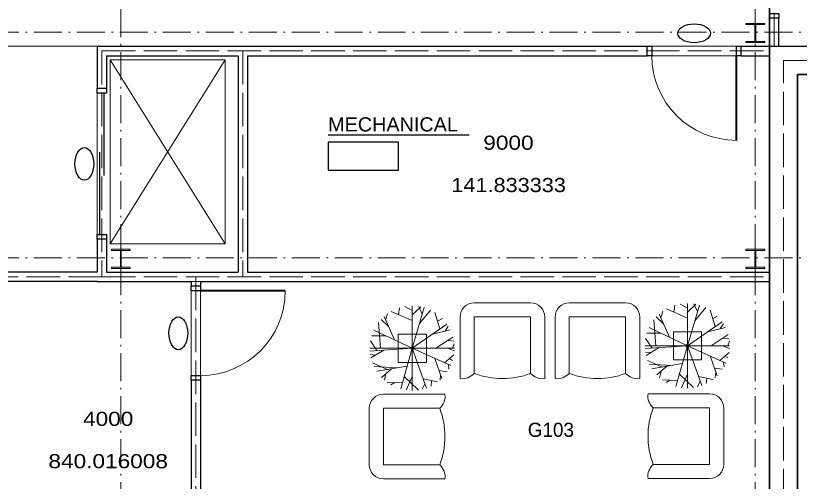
# Model space of a CAD drawing. Extents: x -118748 to -117136, y -118748 to -117596.
# Drawn here: x -117726.1 to -117459.3, y -118491.2 to -118332.8 of the extents above; entities that cross this region are included whole.
import ezdxf
from ezdxf.enums import TextEntityAlignment as Align

# ---------------------------------------------------------------- set-up
doc = ezdxf.new("R2010")
doc.units = 0
doc.header["$LTSCALE"] = 1.9
doc.header["$PDMODE"] = 32
doc.header["$PDSIZE"] = 0.95
doc.linetypes.add('DOT_DASHED', pattern=[7.7, 5, -1.2, 0.3, -1.2])
doc.linetypes.add('LONG_DASHED', pattern=[7.5, 6, -1.5])
for name, color, linetype, lineweight in [('10', 7, 'DOT_DASHED', 13), ('12', 7, 'Continuous', 13), ('15', 7, 'Continuous', 13), ('17', 7, 'Continuous', 25), ('18', 7, 'Continuous', 13), ('23', 7, 'Continuous', 25), ('25', 7, 'Continuous', 13), ('26', 7, 'Continuous', 25), ('3', 7, 'Continuous', 35), ('30', 7, 'Continuous', 13), ('4', 7, 'Continuous', 35), ('42', 7, 'Continuous', 25), ('45', 7, 'Continuous', 25), ('5', 7, 'Continuous', 13), ('6', 7, 'Continuous', 13), ('60', 7, 'LONG_DASHED', 13), ('9', 7, 'Continuous', 35)]:
    doc.layers.add(name, color=color, linetype=linetype, lineweight=lineweight)

msp = doc.modelspace()

# ---------------------------------------------------------------- linework, layer by layer
at = {"layer": '10'}
for p, q in [((-117690.321, -117628.339), (-117690.321, -118698.41)), ((-117474.321, -117628.339), (-117474.321, -118698.41)), ((-118641.571, -118338.41), (-117285.521, -118338.41)), ((-118641.571, -118415.21), (-117285.521, -118415.21))]:
    msp.add_line(p, q, dxfattribs=at)
at = {"layer": '12'}
for points in [[(-117477.504, -118341.962), (-117471.088, -118341.962), (-117471.088, -118341.566), (-117474.172, -118341.566), (-117474.172, -118335.862), (-117471.088, -118335.862), (-117471.088, -118335.466), (-117477.504, -118335.466), (-117477.504, -118335.862), (-117474.42, -118335.862), (-117474.42, -118341.566), (-117477.504, -118341.566)], [(-117693.504, -118418.762), (-117687.088, -118418.762), (-117687.088, -118418.366), (-117690.172, -118418.366), (-117690.172, -118412.662), (-117687.088, -118412.662), (-117687.088, -118412.266), (-117693.504, -118412.266), (-117693.504, -118412.662), (-117690.42, -118412.662), (-117690.42, -118418.366), (-117693.504, -118418.366)], [(-117477.504, -118418.762), (-117471.088, -118418.762), (-117471.088, -118418.366), (-117474.172, -118418.366), (-117474.172, -118412.662), (-117471.088, -118412.662), (-117471.088, -118412.266), (-117477.504, -118412.266), (-117477.504, -118412.662), (-117474.42, -118412.662), (-117474.42, -118418.366), (-117477.504, -118418.366)]]:
    msp.add_lwpolyline(points, close=True, dxfattribs=at)
at = {"layer": '15', "lineweight": 25}
for p, q in [((-117469.521, -118343.21), (-117379.921, -118343.21)), ((-117469.521, -118492.01), (-117469.521, -118343.21)), ((-117459.921, -118352.81), (-117370.321, -118352.81)), ((-117459.921, -118492.01), (-117459.921, -118352.81))]:
    msp.add_line(p, q, dxfattribs=at)
at = {"layer": '15'}
for p, q in [((-117550.78, -118430.474), (-117569.98, -118430.474)), ((-117518.446, -118430.474), (-117537.646, -118430.474)), ((-117574.78, -118435.274), (-117574.78, -118456.259)), ((-117545.98, -118456.259), (-117545.98, -118435.274)), ((-117542.446, -118435.274), (-117542.446, -118456.259)), ((-117513.646, -118456.259), (-117513.646, -118435.274)), ((-117579.946, -118461.557), (-117600.932, -118461.557)), ((-117489.85, -118461.426), (-117510.836, -118461.426)), ((-117605.732, -118466.357), (-117605.732, -118485.557)), ((-117485.05, -118485.426), (-117485.05, -118466.226)), ((-117600.932, -118490.357), (-117579.946, -118490.357)), ((-117510.836, -118490.226), (-117489.85, -118490.226))]:
    msp.add_line(p, q, dxfattribs=at)
for points in [[(-117550.78, -118454.474), (-117550.78, -118435.274), (-117569.98, -118435.274), (-117569.98, -118454.474)], [(-117518.446, -118454.474), (-117518.446, -118435.274), (-117537.646, -118435.274), (-117537.646, -118454.474)], [(-117581.732, -118466.357), (-117600.932, -118466.357), (-117600.932, -118485.557), (-117581.732, -118485.557)], [(-117509.05, -118485.426), (-117489.85, -118485.426), (-117489.85, -118466.226), (-117509.05, -118466.226)]]:
    msp.add_lwpolyline(points, dxfattribs=at)
for centre, radius, start, end in [((-117569.98, -118435.274), 4.8, 90, 180), ((-117550.78, -118435.274), 4.8, 360, 90), ((-117537.646, -118435.274), 4.8, 90, 180), ((-117518.446, -118435.274), 4.8, 360, 90), ((-117574.085, -118450.782), 5.521, 262.77334, 318.03706), ((-117560.38, -118429.56), 26.699, 248.92678, 291.07322), ((-117546.674, -118450.782), 5.521, 221.96294, 277.22666), ((-117541.752, -118450.782), 5.521, 262.77334, 318.03706), ((-117528.046, -118429.56), 26.699, 248.92678, 291.07322), ((-117514.341, -118450.782), 5.521, 221.96294, 277.22666), ((-117600.932, -118466.357), 4.8, 90, 180), ((-117585.423, -118462.252), 5.521, 311.96294, 7.22666), ((-117505.358, -118462.12), 5.521, 172.77334, 228.03706), ((-117489.85, -118466.226), 4.8, 360, 90), ((-117606.645, -118475.957), 26.699, 338.92678, 21.07322), ((-117484.136, -118475.826), 26.699, 158.92678, 201.07321), ((-117600.932, -118485.557), 4.8, 180, 270), ((-117585.423, -118489.663), 5.521, 352.77334, 48.03706), ((-117505.358, -118489.531), 5.521, 131.96294, 187.22666), ((-117489.85, -118485.426), 4.8, 270, 0)]:
    msp.add_arc(centre, radius, start, end, dxfattribs=at)
at = {"layer": '17'}
msp.add_line((-117619.741, -118373.375), (-117571.741, -118373.375), dxfattribs=at)
at = {"layer": '18'}
for p, q in [((-117693.869, -118347.778), (-117654.831, -118410.353)), ((-117693.869, -118410.353), (-117654.831, -118347.778))]:
    msp.add_line(p, q, dxfattribs=at)
msp.add_lwpolyline([(-117693.869, -118347.778), (-117693.869, -118410.353), (-117654.831, -118410.353), (-117654.831, -118347.778)], close=True, dxfattribs=at)
at = {"layer": '23'}
for p, q in [((-117466.321, -118333.61), (-117469.521, -118333.61)), ((-117469.521, -118343.21), (-117469.521, -118333.61)), ((-117466.321, -118343.21), (-117466.321, -118333.61)), ((-117698.321, -118343.21), (-117698.321, -118357.61)), ((-117698.321, -118343.21), (-117511.121, -118343.21)), ((-117511.121, -118346.41), (-117511.121, -118343.21)), ((-117479.121, -118346.41), (-117479.121, -118343.21)), ((-117479.121, -118343.21), (-117469.521, -118343.21)), ((-117469.521, -118343.21), (-117466.321, -118343.21)), ((-117695.121, -118346.41), (-117650.321, -118346.41)), ((-117695.121, -118346.41), (-117695.121, -118357.61)), ((-117650.321, -118346.41), (-117650.321, -118420.01)), ((-117647.121, -118346.41), (-117647.121, -118420.01)), ((-117647.121, -118346.41), (-117511.121, -118346.41)), ((-117479.121, -118346.41), (-117469.521, -118346.41)), ((-117695.121, -118357.61), (-117698.321, -118357.61)), ((-117695.121, -118408.81), (-117698.321, -118408.81)), ((-117698.321, -118408.81), (-117698.321, -118420.01)), ((-117695.121, -118408.81), (-117695.121, -118420.01)), ((-117698.321, -118420.01), (-117843.25, -118420.01)), ((-117695.121, -118420.01), (-117650.321, -118420.01)), ((-117647.121, -118420.01), (-117469.521, -118420.01)), ((-117469.521, -118420.01), (-117469.521, -118423.21)), ((-117698.321, -118423.21), (-117840.35, -118423.21)), ((-117698.321, -118423.21), (-117666.321, -118423.21)), ((-117666.321, -118423.21), (-117666.321, -118424.81)), ((-117663.121, -118424.81), (-117666.321, -118424.81)), ((-117663.121, -118423.21), (-117469.521, -118423.21)), ((-117663.121, -118423.21), (-117663.121, -118424.81)), ((-117663.121, -118456.81), (-117666.321, -118456.81)), ((-117666.321, -118456.81), (-117666.321, -118588.01)), ((-117663.121, -118456.81), (-117663.121, -118600.81))]:
    msp.add_line(p, q, dxfattribs=at)
at = {"layer": '25', "lineweight": 40}
for p, q in [((-117480.721, -118375.21), (-117480.721, -118346.41)), ((-117634.321, -118426.41), (-117663.121, -118426.41))]:
    msp.add_line(p, q, dxfattribs=at)
at = {"layer": '25', "lineweight": 25}
for p, q in [((-117695.921, -118387.209), (-117695.921, -118359.209)), ((-117697.488, -118407.181), (-117697.488, -118379.181))]:
    msp.add_line(p, q, dxfattribs=at)
at = {"layer": '25'}
for centre, start, end in [((-117480.721, -118346.41), 180.00001, 270), ((-117663.121, -118426.41), 270.00001, 0)]:
    msp.add_arc(centre, 28.8, start, end, dxfattribs=at)
at = {"layer": '26'}
for points in [[(-117469.521, -118333.61), (-117469.521, -118332.01), (-117466.321, -118332.01), (-117466.321, -118333.61)], [(-117511.121, -118343.21), (-117509.521, -118343.21), (-117509.521, -118346.41), (-117511.121, -118346.41)], [(-117479.121, -118346.41), (-117480.721, -118346.41), (-117480.721, -118343.21), (-117479.121, -118343.21)], [(-117695.121, -118357.61), (-117695.121, -118359.21), (-117698.321, -118359.21), (-117698.321, -118357.61)], [(-117698.321, -118408.81), (-117698.321, -118407.21), (-117695.121, -118407.21), (-117695.121, -118408.81)], [(-117663.121, -118424.81), (-117663.121, -118426.41), (-117666.321, -118426.41), (-117666.321, -118424.81)], [(-117666.321, -118456.81), (-117666.321, -118455.21), (-117663.121, -118455.21), (-117663.121, -118456.81)]]:
    msp.add_lwpolyline(points, dxfattribs=at)
at = {"layer": '3'}
msp.add_lwpolyline([(-118098.321, -117954.41), (-117829.521, -117954.41), (-117459.921, -117954.41), (-117459.921, -118170.41), (-117370.321, -118170.41), (-117370.321, -118352.81), (-117459.921, -118352.81), (-117459.921, -118645.61), (-117704.721, -118645.61), (-117704.721, -118592.81), (-117847.121, -118592.81), (-117850.321, -118592.801), (-117860.744, -118590.984), (-117862.249, -118590.443), (-117871.571, -118585.668), (-117872.847, -118584.703), (-117880.323, -118577.368), (-117881.254, -118576.067), (-117886.205, -118566.837), (-117886.706, -118565.318), (-117888.682, -118555.032), (-117888.707, -118553.433), (-117890.316, -118553.433)], dxfattribs=at)
at = {"layer": '30'}
for p, q in [((-117595.726, -118434.473), (-117595.401, -118432.155)), ((-117591.128, -118433.07), (-117593.566, -118431.715)), ((-117591.128, -118460.307), (-117591.128, -118431.507)), ((-117591.128, -118434.504), (-117588.22, -118431.804)), ((-117591.128, -118445.907), (-117587.042, -118432.099)), ((-117587.691, -118434.291), (-117588.876, -118431.684)), ((-117588.633, -118437.476), (-117584.862, -118432.941)), ((-117497.443, -118435.647), (-117504.548, -118432.553)), ((-117502.042, -118433.644), (-117501.716, -118431.326)), ((-117497.443, -118432.241), (-117499.881, -118430.886)), ((-117497.443, -118459.478), (-117497.443, -118430.678)), ((-117497.443, -118433.675), (-117494.535, -118430.974)), ((-117497.443, -118445.078), (-117493.357, -118431.27)), ((-117494.006, -118433.462), (-117495.192, -118430.855)), ((-117494.948, -118436.647), (-117491.178, -118432.112)), ((-117487.968, -118438.537), (-117489.714, -118432.928)), ((-117597.189, -118443.025), (-117600.688, -118435.138)), ((-117600.149, -118436.354), (-117599.487, -118434.182)), ((-117591.128, -118436.476), (-117598.233, -118433.382)), ((-117581.653, -118439.366), (-117583.399, -118433.757)), ((-117582.489, -118436.679), (-117580.822, -118435.849)), ((-117505.516, -118437.661), (-117508.01, -118435.295)), ((-117503.504, -118442.196), (-117507.003, -118434.309)), ((-117506.464, -118435.524), (-117505.803, -118433.353)), ((-117488.805, -118435.85), (-117487.138, -118435.02)), ((-117601.849, -118445.907), (-117602.53, -118437.111)), ((-117599.201, -118438.49), (-117601.695, -118436.124)), ((-117591.128, -118445.907), (-117579.277, -118437.727)), ((-117579.908, -118440.081), (-117578.827, -118438.42)), ((-117508.165, -118445.078), (-117508.845, -118436.282)), ((-117497.443, -118445.078), (-117485.592, -118436.897)), ((-117486.224, -118439.252), (-117485.143, -118437.591)), ((-117591.128, -118445.907), (-117604.133, -118439.724)), ((-117584.191, -118441.118), (-117578.155, -118439.657)), ((-117506.383, -118440.827), (-117511.202, -118440.83)), ((-117497.443, -118445.078), (-117510.448, -118438.895)), ((-117490.506, -118440.289), (-117484.47, -118438.827)), ((-117603.141, -118446.716), (-117605.316, -118443.446)), ((-117600.068, -118441.657), (-117604.887, -118441.659)), ((-117583.06, -118445.907), (-117577.236, -118442.115)), ((-117579.107, -118443.333), (-117576.929, -118443.511)), ((-117509.457, -118445.887), (-117511.631, -118442.617)), ((-117489.375, -118445.078), (-117483.551, -118441.286)), ((-117485.422, -118442.504), (-117483.244, -118442.681)), ((-117483.71, -118445.078), (-117483.123, -118443.563)), ((-117576.728, -118445.907), (-117605.528, -118445.907)), ((-117591.128, -118445.907), (-117605.495, -118446.874)), ((-117600.714, -118446.552), (-117605.148, -118449.193)), ((-117591.128, -118445.907), (-117595.027, -118459.769)), ((-117591.128, -118445.907), (-117577.993, -118451.809)), ((-117591.128, -118445.907), (-117586.244, -118459.453)), ((-117579.115, -118445.907), (-117576.758, -118446.843)), ((-117577.394, -118445.907), (-117576.808, -118444.392)), ((-117483.043, -118445.078), (-117511.843, -118445.078)), ((-117497.443, -118445.078), (-117511.811, -118446.045)), ((-117507.029, -118445.723), (-117511.463, -118448.364)), ((-117497.443, -118445.078), (-117501.342, -118458.94)), ((-117497.443, -118445.078), (-117484.308, -118450.98)), ((-117497.443, -118445.078), (-117492.559, -118458.624)), ((-117485.431, -118445.078), (-117483.074, -118446.014)), ((-117603.537, -118448.233), (-117605.366, -118448.061)), ((-117580.08, -118450.871), (-117576.91, -118448.187)), ((-117509.852, -118447.404), (-117511.681, -118447.232)), ((-117489.705, -118448.555), (-117487.333, -118455.331)), ((-117486.395, -118450.042), (-117483.225, -118447.358)), ((-117484.7, -118448.607), (-117483.657, -118449.238)), ((-117599.557, -118453.133), (-117604.646, -118450.87)), ((-117583.389, -118449.384), (-117581.017, -118456.16)), ((-117578.77, -118451.459), (-117578.621, -118453.043)), ((-117578.385, -118449.437), (-117577.342, -118450.067)), ((-117505.873, -118452.304), (-117510.961, -118450.04)), ((-117502.618, -118451.748), (-117510.415, -118451.33)), ((-117499.153, -118451.156), (-117509.516, -118452.927)), ((-117485.086, -118450.63), (-117484.936, -118452.214)), ((-117596.303, -118452.577), (-117604.1, -118452.159)), ((-117592.837, -118451.985), (-117603.201, -118453.756)), ((-117598.128, -118452.889), (-117601.547, -118455.847)), ((-117600.059, -118454.56), (-117600.585, -118456.766)), ((-117581.952, -118453.489), (-117579.157, -118453.911)), ((-117504.443, -118452.06), (-117507.862, -118455.018)), ((-117506.374, -118453.73), (-117506.9, -118455.937)), ((-117488.268, -118452.66), (-117485.473, -118453.082)), ((-117487.763, -118454.102), (-117487.946, -118455.902)), ((-117593.839, -118455.547), (-117588.985, -118460.146)), ((-117591.128, -118455.588), (-117593.129, -118460.167)), ((-117587.361, -118456.357), (-117582.441, -118457.392)), ((-117584.521, -118456.954), (-117584.688, -118458.787)), ((-117581.448, -118454.931), (-117581.63, -118456.731)), ((-117500.764, -118456.885), (-117505.943, -118456.701)), ((-117503.359, -118456.793), (-117504.668, -118457.534)), ((-117500.154, -118454.717), (-117495.3, -118459.317)), ((-117497.443, -118454.759), (-117499.445, -118459.338)), ((-117493.092, -118457.147), (-117493.984, -118459.056)), ((-117493.676, -118455.527), (-117488.757, -118456.563)), ((-117490.837, -118456.125), (-117491.003, -118457.958)), ((-117594.448, -118457.714), (-117599.628, -118457.531)), ((-117597.044, -118457.622), (-117598.353, -118458.363)), ((-117586.777, -118457.976), (-117587.669, -118459.885))]:
    msp.add_line(p, q, dxfattribs=at)
for points in [[(-117586.28, -118450.75), (-117595.88, -118450.75), (-117595.88, -118441.15), (-117586.28, -118441.15)], [(-117492.595, -118449.921), (-117502.195, -118449.921), (-117502.195, -118440.321), (-117492.595, -118440.321)]]:
    msp.add_lwpolyline(points, close=True, dxfattribs=at)
for p in [(-117591.128, -118445.907), (-117497.443, -118445.078)]:
    msp.add_point(p, dxfattribs=at)
at = {"layer": '4'}
msp.add_lwpolyline([(-118496.721, -117964.01), (-118496.721, -118636.01), (-118271.121, -118636.01), (-118271.121, -118588.01), (-118115.969, -118588.01), (-118106.1, -118586.234), (-118096.66, -118581.314), (-118089.115, -118573.804), (-118084.156, -118564.399), (-118081.154, -118548.633), (-118079.134, -118548.633), (-117884.057, -118548.587), (-117881.646, -118565.336), (-117876.897, -118574.111), (-117869.271, -118581.538), (-117859.789, -118586.351), (-117850.271, -118588.01), (-117695.121, -118588.01), (-117695.121, -118636.01), (-117469.521, -118636.01), (-117469.521, -117964.01)], close=True, dxfattribs=at)
at = {"layer": '42'}
for centre, major_axis in [((-117495.121, -118338.81), (-5.6, 0)), ((-117702.721, -118383.21), (0, -5.6)), ((-117670.721, -118440.81), (0, -5.6))]:
    msp.add_ellipse(centre, major_axis=major_axis, ratio=0.571429, dxfattribs=at)
at = {"layer": '45'}
msp.add_lwpolyline([(-117619.741, -118375.775), (-117619.741, -118385.375), (-117595.741, -118385.375), (-117595.741, -118375.775)], close=True, dxfattribs=at)
at = {"layer": '5'}
for points in [[(-117979.078, -117964.01), (-117469.521, -117964.01), (-117469.521, -118636.01), (-117695.121, -118636.01), (-117695.121, -118588.01), (-117850.271, -118588.01)], [(-117843.071, -118184.81), (-117843.071, -118295.21), (-117503.121, -118295.21), (-117469.521, -118295.21), (-117469.521, -118301.61), (-117469.521, -118343.21), (-117479.121, -118343.21), (-117698.321, -118343.21), (-117698.321, -118357.61), (-117698.321, -118420.01), (-117843.25, -118420.01)], [(-117840.35, -118423.21), (-117666.321, -118423.21), (-117666.321, -118456.81), (-117666.321, -118588.01), (-117706.321, -118588.01), (-117847.121, -118588.01), (-117850.321, -118588.001), (-117859.12, -118586.467), (-117860.626, -118585.926), (-117868.676, -118581.84), (-117869.952, -118580.875), (-117876.419, -118574.577), (-117877.349, -118573.275), (-117881.646, -118565.336), (-117882.147, -118563.816), (-117883.883, -118554.958), (-117883.908, -118477.769)]]:
    msp.add_lwpolyline(points, dxfattribs=at)
msp.add_lwpolyline([(-117663.121, -118636.01), (-117663.121, -118632.81), (-117663.121, -118423.21), (-117469.521, -118423.21), (-117469.521, -118636.01)], close=True, dxfattribs=at)
at = {"layer": '6'}
for points in [[(-117843.071, -118184.81), (-117843.071, -118343.21), (-117698.321, -118343.21), (-117698.321, -118420.01), (-117843.25, -118420.01)], [(-117850.321, -118588.001), (-117695.121, -118588.01), (-117695.121, -118636.01), (-117469.521, -118636.01), (-117469.521, -118423.21), (-117840.35, -118423.21)]]:
    msp.add_lwpolyline(points, dxfattribs=at)
for points in [[(-117843.071, -118295.21), (-117469.521, -118295.21), (-117469.521, -118343.21), (-117843.071, -118343.21)], [(-117647.121, -118346.41), (-117469.521, -118346.41), (-117469.521, -118420.01), (-117647.121, -118420.01)]]:
    msp.add_lwpolyline(points, close=True, dxfattribs=at)
at = {"layer": '60'}
for p, q in [((-117467.921, -118343.21), (-117467.921, -118180.01)), ((-117696.721, -118344.81), (-117469.521, -118344.81)), ((-117648.721, -118344.81), (-117648.721, -118421.61)), ((-117696.721, -118421.61), (-117841.784, -118421.61)), ((-117664.721, -118421.61), (-117664.721, -118636.01))]:
    msp.add_line(p, q, dxfattribs=at)
for points in [[(-117696.721, -118344.81), (-117696.721, -118421.61), (-117469.521, -118421.61)], [(-117464.721, -118640.81), (-117464.721, -118348.01), (-117375.121, -118348.01)]]:
    msp.add_lwpolyline(points, dxfattribs=at)

# ---------------------------------------------------------------- texts
at = {"layer": '17', "width": 1.05}
msp.add_text('MECHANICAL', height=4.8, dxfattribs=at).set_placement((-117619.741, -118372.175))
at = {"layer": '45'}
for s, width, p in [('9000', 1.2, (-117558.34, -118378.41)), ('141.833333', 1.15, (-117558.283, -118392.81)), ('4000', 1.2, (-117694.598, -118472.332)), ('840.016008', 1.2, (-117694.598, -118486.732))]:
    msp.add_text(s, height=4.8, dxfattribs=dict(at, width=width)).set_placement(p, align=Align.CENTER)
at = {"layer": '9'}
msp.add_text('G103', height=4.8, dxfattribs=at).set_placement((-117543.908, -118476.06), align=Align.CENTER)

doc.saveas('drawing.dxf')
